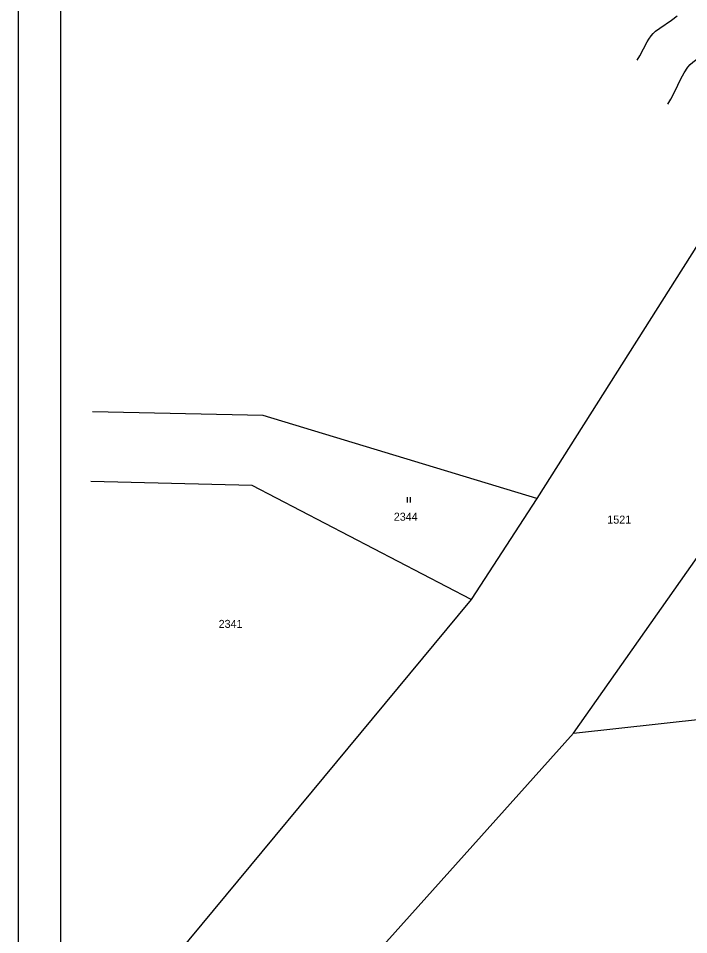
# Model space of a CAD drawing. Extents: x -792549 to -792339, y -1111914 to -1111617.
# Drawn here: x -792548.6 to -792500.8, y -1111801.9 to -1111736.6 of the extents above; entities that cross this region are included whole.
import ezdxf

# ---------------------------------------------------------------- set-up
doc = ezdxf.new("R2010")
doc.units = 0
for name, color, linetype in [('Vrstva 1', 7, 'Continuous'), ('Vrstva 24', 7, 'Continuous'), ('Vrstva 32', 7, 'Continuous'), ('Vrstva 33', 7, 'Continuous'), ('Vrstva 41', 7, 'Continuous'), ('Vrstva 42', 7, 'Continuous'), ('Vrstva 60', 7, 'Continuous')]:
    doc.layers.add(name, color=color, linetype=linetype)

# ---------------------------------------------------------------- blocks, each defined once
blk = doc.blocks.new('3$0600')
at = {"layer": 'Vrstva 1'}
for p, q in [((-5, 15), (-5, 0)), ((5, 0), (5, 15))]:
    blk.add_line(p, q, dxfattribs=at)

msp = doc.modelspace()

# ---------------------------------------------------------------- linework, layer by layer
at = {"layer": 'Vrstva 24'}
msp.add_lwpolyline([(-792545.564, -1111620.164), (-792545.564, -1111911.164), (-792341.564, -1111911.164), (-792341.564, -1111620.164)], close=True, dxfattribs=at)
at = {"layer": 'Vrstva 32'}
msp.add_lwpolyline([(-792502.309, -1111742.735), (-792502.096, -1111742.379), (-792501.818, -1111741.83), (-792501.392, -1111740.929), (-792501.16, -1111740.499), (-792500.894, -1111740.106), (-792500.731, -1111739.92), (-792500.546, -1111739.75), (-792499.649, -1111739.07), (-792499.356, -1111738.822), (-792499.093, -1111738.563), (-792498.928, -1111738.371), (-792498.775, -1111738.163), (-792498.578, -1111737.836), (-792498.451, -1111737.583), (-792498.188, -1111736.964), (-792497.952, -1111736.315)], dxfattribs=at)
at = {"layer": 'Vrstva 33'}
msp.add_lwpolyline([(-792504.497, -1111739.612), (-792504.303, -1111739.289), (-792503.798, -1111738.305), (-792503.674, -1111738.098), (-792503.509, -1111737.871), (-792503.371, -1111737.717), (-792503.184, -1111737.55), (-792502.888, -1111737.326), (-792502.052, -1111736.758), (-792501.652, -1111736.453)], dxfattribs=at)
at = {"layer": 'Vrstva 41'}
for points in [[(-792537.3, -1111819.066), (-792509.03, -1111787.52), (-792494.7, -1111767.15), (-792487.93, -1111755.84), (-792488.57, -1111751.6), (-792481.63, -1111739.54), (-792474.4, -1111729.01), (-792471.44, -1111725.75), (-792468.11, -1111720.8), (-792469.49, -1111708.06)], [(-792480.39, -1111721.44), (-792511.65, -1111770.81), (-792516.32, -1111777.99), (-792542.554, -1111809.622)], [(-792511.65, -1111770.81), (-792531.13, -1111764.91), (-792543.284, -1111764.649)], [(-792516.32, -1111777.99), (-792531.92, -1111769.89), (-792543.407, -1111769.605)], [(-792509.03, -1111787.52), (-792496.54, -1111786.14), (-792481.82, -1111799.75), (-792477.95, -1111789.03)]]:
    msp.add_lwpolyline(points, dxfattribs=at)
at = {"layer": 'Vrstva 60'}
msp.add_lwpolyline([(-792548.564, -1111617.164), (-792548.564, -1111914.164), (-792338.564, -1111914.164), (-792338.564, -1111617.164), (-792548.564, -1111617.164)], dxfattribs=at)

# ---------------------------------------------------------------- block references
at = {"layer": 'Vrstva 42', "xscale": 0.024999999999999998, "yscale": 0.025, "rotation": 0.10962822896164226}
msp.add_blockref('3$0600', (-792520.76, -1111771.102), dxfattribs=at)

# ---------------------------------------------------------------- texts
at = {"layer": 'Vrstva 42'}
for s, p in [('2344', (-792521.826, -1111772.392)), ('1521', (-792506.625, -1111772.6)), ('2341', (-792534.3, -1111780.023))]:
    msp.add_text(s, height=0.57, dxfattribs=at).set_placement(p)

doc.saveas('drawing.dxf')
